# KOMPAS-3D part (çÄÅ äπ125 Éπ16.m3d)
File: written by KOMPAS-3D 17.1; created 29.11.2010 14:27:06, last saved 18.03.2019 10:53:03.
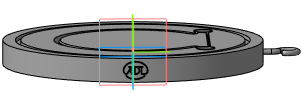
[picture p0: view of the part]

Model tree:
1. Плоскость XY
2. Плоскость ZX
3. Плоскость ZY
4. Ось X
5. Ось Y
6. Ось Z
7. Начало координат
8. Операция без истории:2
